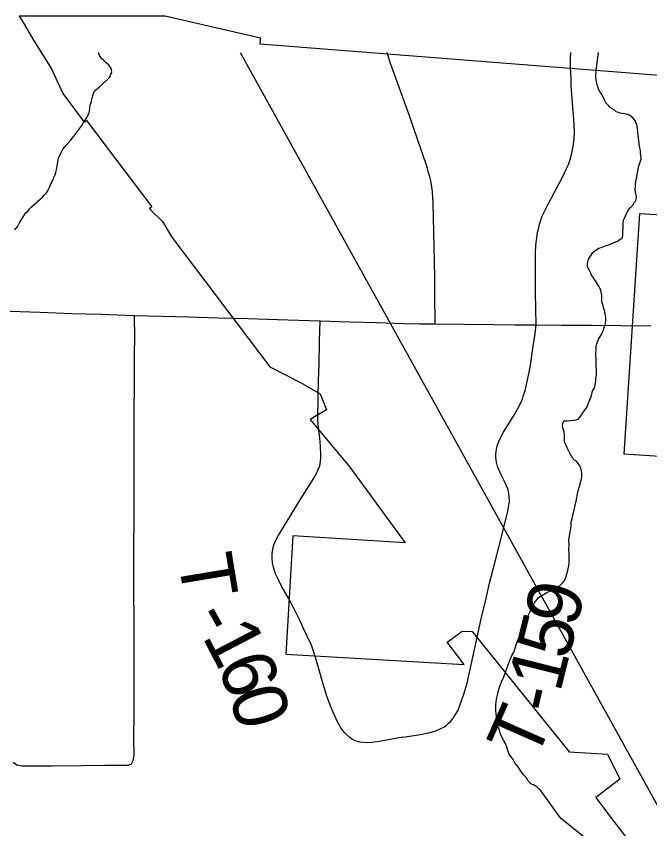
# Model space of a CAD drawing. Extents: x -11.4 to 84.1, y 11.1 to 59.
# Drawn here: x 27.637 to 28.301, y 46.596 to 47.448 of the extents above; entities that cross this region are included whole.
import ezdxf

# ---------------------------------------------------------------- set-up
doc = ezdxf.new("R2010")
doc.units = 0
for name, color, linetype in [('GM_X_Corporation', 7, 'Continuous'), ('GM_X_Minor_River', 7, 'Continuous'), ('GM_X_Rail_Line', 7, 'Continuous'), ('GM_X_Township_Road', 7, 'Continuous'), ('GM_X_Township_Road_Text', 7, 'Continuous')]:
    doc.layers.add(name, color=color, linetype=linetype)

msp = doc.modelspace()

# ---------------------------------------------------------------- linework, layer by layer
at = {"layer": 'GM_X_Corporation'}
msp.add_line((27.79268, 47.44833), (27.63977, 47.44833), dxfattribs=at)
for points in [[(27.63977, 47.44833), (27.64249, 47.4443), (27.6547, 47.42315), (27.67347, 47.39312), (27.68548, 47.36738), (27.70805, 47.33744), (27.71029, 47.33919), (27.77869, 47.24846), (27.77645, 47.24671), (27.77782, 47.2449), (27.78994, 47.23319), (27.79979, 47.2168), (27.90239, 47.08071), (27.93479, 47.06422), (27.95529, 47.05239), (27.96203, 47.03571), (27.95104, 47.02936), (27.94478, 47.02544), (27.98632, 46.97547), (28.04447, 46.89618), (27.92669, 46.90354), (27.91934, 46.77964), (28.1062, 46.76855), (28.08852, 46.79203), (28.1041, 46.80376), (28.11456, 46.8031), (28.21645, 46.67717), (28.25658, 46.67474), (28.26956, 46.64831), (28.24424, 46.62928), (28.25971, 46.6087), (28.38036, 46.45198)], [(28.44546, 47.44833), (28.44455, 47.44112), (28.53898, 47.43662), (28.53548, 47.37236), (28.42679, 47.37725), (27.89224, 47.41905), (27.89257, 47.4253), (27.79268, 47.44833)], [(28.2903, 47.24157), (28.42072, 47.2334), (28.42172, 47.24957), (28.5648, 47.24008), (28.55737, 47.12683), (28.7946, 47.11346), (28.77683, 46.76871), (28.73379, 46.77147), (28.74706, 46.99577), (28.65864, 47.00186), (28.65525, 46.95254), (28.60594, 46.95577), (28.60858, 47.01026), (28.59714, 47.01103), (28.59712, 47.01103), (28.59707, 47.01009), (28.49816, 47.01681), (28.40014, 47.02337), (28.39736, 46.98115), (28.27402, 46.98922), (28.2903, 47.24157)]]:
    msp.add_lwpolyline(points, dxfattribs=at)
at = {"layer": 'GM_X_Minor_River'}
for points in [[(27.63524, 47.22449), (27.63824, 47.22832), (27.6401, 47.23176), (27.64234, 47.2352), (27.64458, 47.23903), (27.64682, 47.24209), (27.6487, 47.24401), (27.6502, 47.24593), (27.65283, 47.24862), (27.66148, 47.25631), (27.66412, 47.25861), (27.66637, 47.26092), (27.66825, 47.26322), (27.67011, 47.2659), (27.67123, 47.26819), (27.67234, 47.27086), (27.67345, 47.27315), (27.67494, 47.27621), (27.67604, 47.27926), (27.67753, 47.28194), (27.67826, 47.28461), (27.67899, 47.28728), (27.6797, 47.29147), (27.68042, 47.29527), (27.68113, 47.29947), (27.68261, 47.30328), (27.68409, 47.30634), (27.68558, 47.30901), (27.68745, 47.31131), (27.68971, 47.314), (27.69308, 47.31783), (27.69571, 47.3209), (27.69833, 47.32435), (27.70095, 47.32742), (27.70319, 47.33086), (27.70544, 47.33392), (27.70768, 47.33775), (27.70954, 47.34043), (27.71066, 47.34234), (27.71178, 47.34425), (27.7129, 47.34617), (27.71363, 47.34883), (27.71397, 47.35188), (27.71431, 47.35531), (27.71541, 47.35912), (27.71613, 47.36293), (27.71723, 47.36636), (27.71834, 47.36903), (27.72021, 47.37133), (27.7236, 47.37403), (27.733, 47.38287), (27.73489, 47.3844), (27.73599, 47.38746), (27.73673, 47.38937), (27.7367, 47.39203), (27.73591, 47.3943), (27.7336, 47.39694), (27.73091, 47.39957), (27.72898, 47.40145), (27.7263, 47.40371), (27.72398, 47.40711), (27.72319, 47.40938), (27.72318, 47.41026)], [(28.28767, 47.28271), (28.28839, 47.28576), (28.2891, 47.29033), (28.29167, 47.29834), (28.29164, 47.30062), (28.29122, 47.30442), (28.29118, 47.30746), (28.29039, 47.31049), (28.28958, 47.31429), (28.28916, 47.31809), (28.28872, 47.32302), (28.28829, 47.3272), (28.28788, 47.33024), (28.28747, 47.3329), (28.28706, 47.33517), (28.28628, 47.33707), (28.28549, 47.33896), (28.28318, 47.34198), (28.27973, 47.34422), (28.27782, 47.34535), (28.27477, 47.34608), (28.27172, 47.34642), (28.26982, 47.34679), (28.26791, 47.34753), (28.26562, 47.34827), (28.2637, 47.34977), (28.2614, 47.35126), (28.2591, 47.35276), (28.25756, 47.35465), (28.25486, 47.35766), (28.2537, 47.35955), (28.25253, 47.3622), (28.25097, 47.36599), (28.24865, 47.36863), (28.24709, 47.37203), (28.24591, 47.37544), (28.24511, 47.37962), (28.24428, 47.38531), (28.24459, 47.3914), (28.24701, 47.41026)], [(28.21265, 46.99909), (28.21148, 47.00213), (28.21145, 47.00441), (28.21143, 47.00631), (28.2114, 47.00859), (28.21138, 47.01049), (28.21058, 47.0139), (28.20978, 47.01694), (28.20937, 47.01959), (28.20973, 47.0215), (28.21084, 47.02417), (28.21388, 47.0242), (28.22375, 47.02506), (28.22565, 47.02584), (28.22828, 47.02853), (28.22976, 47.03158), (28.23238, 47.03503), (28.235, 47.03886), (28.23684, 47.04382), (28.23907, 47.04878), (28.24089, 47.05527), (28.24275, 47.05871), (28.24348, 47.06138), (28.24383, 47.06404), (28.24419, 47.06595), (28.24416, 47.06823), (28.24452, 47.07013), (28.24486, 47.07356), (28.24481, 47.07774), (28.24475, 47.08268), (28.24469, 47.08838), (28.24424, 47.09408), (28.24456, 47.09979), (28.24452, 47.10245), (28.24562, 47.10588), (28.2471, 47.1097), (28.25008, 47.11467), (28.25231, 47.11963), (28.25377, 47.12421), (28.25486, 47.1284), (28.25482, 47.13259), (28.25442, 47.13448), (28.25401, 47.13638), (28.25321, 47.13979), (28.25242, 47.14283), (28.25162, 47.14624), (28.25044, 47.14927), (28.25042, 47.15155), (28.25038, 47.15421), (28.25036, 47.15611), (28.24995, 47.15877), (28.24954, 47.16143), (28.24838, 47.16332), (28.24722, 47.16521), (28.24605, 47.16748), (28.2445, 47.16974), (28.24102, 47.17503), (28.23986, 47.17692), (28.23908, 47.17881), (28.23752, 47.18184), (28.23635, 47.18411), (28.23557, 47.18638), (28.23554, 47.18866), (28.23589, 47.19095), (28.23662, 47.19362), (28.23849, 47.19668), (28.2411, 47.2005), (28.24449, 47.20358), (28.24751, 47.20513), (28.24978, 47.20591), (28.25168, 47.20669), (28.25508, 47.20787), (28.25849, 47.20904), (28.26265, 47.2106), (28.26681, 47.21255), (28.26983, 47.21448), (28.27172, 47.21526), (28.27244, 47.21869), (28.2724, 47.22249), (28.27273, 47.22667), (28.27305, 47.232), (28.2734, 47.23467), (28.27451, 47.23734), (28.27525, 47.23924), (28.27673, 47.2423), (28.2786, 47.24536), (28.28085, 47.24804), (28.2831, 47.25035), (28.28459, 47.25302), (28.28609, 47.25494), (28.28645, 47.25684), (28.2868, 47.25913), (28.2864, 47.26103), (28.28599, 47.26369), (28.28557, 47.26672), (28.28592, 47.26977), (28.28589, 47.27205), (28.28624, 47.27433), (28.28659, 47.277), (28.28732, 47.27967), (28.28767, 47.28271)], [(28.20688, 46.60833), (28.18607, 46.63688), (28.18261, 46.63989), (28.17878, 46.64251), (28.1761, 46.64363), (28.17302, 46.64702), (28.17109, 46.65004), (28.16839, 46.65306), (28.16569, 46.65683), (28.16297, 46.66136), (28.1595, 46.66551), (28.15679, 46.67005), (28.15486, 46.67269), (28.15293, 46.67533), (28.15213, 46.67836), (28.15095, 46.68216), (28.14938, 46.68594), (28.14744, 46.68934), (28.1455, 46.69313), (28.14393, 46.69691), (28.14275, 46.7007), (28.14157, 46.70411), (28.1399, 46.71664), (28.13947, 46.72082), (28.13941, 46.72652), (28.1401, 46.73223), (28.14119, 46.73643), (28.14191, 46.73986), (28.14338, 46.74481), (28.14521, 46.75053), (28.14781, 46.75588), (28.14966, 46.76046), (28.15223, 46.76847), (28.15444, 46.77382), (28.15629, 46.77802), (28.15816, 46.78146), (28.15963, 46.78566), (28.1611, 46.79023), (28.16294, 46.79481), (28.16442, 46.79863), (28.16589, 46.80283), (28.16774, 46.80741), (28.16922, 46.81122), (28.17106, 46.81619), (28.17329, 46.82001), (28.17553, 46.82421), (28.17702, 46.82689), (28.17814, 46.8288), (28.17887, 46.83109), (28.18035, 46.83415), (28.1826, 46.83683), (28.1841, 46.83875), (28.1875, 46.84106), (28.18938, 46.84222), (28.19278, 46.84416), (28.19618, 46.84571), (28.19959, 46.84727), (28.20262, 46.84844), (28.2045, 46.8496), (28.20676, 46.8519), (28.20902, 46.85382), (28.21089, 46.85612), (28.21238, 46.85918), (28.21384, 46.86376), (28.2153, 46.86909), (28.21638, 46.87443), (28.21633, 46.87899), (28.21627, 46.88431), (28.21583, 46.88925), (28.21615, 46.8942), (28.21609, 46.89952), (28.21821, 46.91323), (28.21854, 46.91779), (28.21962, 46.92313), (28.22034, 46.92656), (28.22107, 46.92922), (28.22179, 46.93227), (28.22251, 46.93608), (28.2236, 46.93989), (28.22432, 46.94332), (28.22504, 46.94751), (28.22612, 46.95209), (28.22722, 46.95552), (28.22795, 46.95819), (28.22868, 46.96086), (28.22904, 46.96314), (28.22939, 46.96581), (28.22972, 46.96999), (28.22892, 46.97264), (28.22852, 46.97492), (28.22736, 46.97681), (28.2258, 46.97946), (28.22388, 46.98172), (28.2212, 46.98321), (28.22003, 46.98548), (28.2181, 46.98812), (28.21616, 46.99153), (28.21421, 46.99569), (28.21265, 46.99909)], [(28.20688, 46.60833), (28.23212, 46.58796)]]:
    msp.add_lwpolyline(points, dxfattribs=at)
at = {"layer": 'GM_X_Rail_Line'}
msp.add_lwpolyline([(27.87133, 47.41026), (28.31469, 46.60998), (28.35442, 46.5561), (28.38709, 46.51724), (28.411, 46.50365), (28.46901, 46.49304), (28.59999, 46.44188), (28.7266, 46.38884), (28.90686, 46.29962), (28.96424, 46.27341), (29.02225, 46.26967), (29.04408, 46.28589), (29.07776, 46.34829), (29.09959, 46.38323), (29.13452, 46.40756), (29.16446, 46.41567), (29.23369, 46.40569), (29.32475, 46.39009), (29.40646, 46.38884)], dxfattribs=at)
at = {"layer": 'GM_X_Township_Road'}
for points in [[(28.07597, 47.12574), (28.07554, 47.15681), (28.0753, 47.17394), (28.07506, 47.19107), (28.07436, 47.22185), (28.07366, 47.25264), (28.07347, 47.25773), (28.07286, 47.26451), (28.07229, 47.269), (28.07111, 47.27569), (28.07012, 47.28012), (28.06899, 47.28451), (28.06771, 47.28885), (28.06629, 47.29315), (28.05752, 47.31856), (28.04876, 47.34397), (28.03875, 47.37195), (28.02875, 47.39995), (28.02538, 47.41026)], [(28.18157, 47.12471), (28.18136, 47.14178), (28.18114, 47.15885), (28.18102, 47.17637), (28.1809, 47.1939), (28.18109, 47.20042), (28.18133, 47.20804), (28.18152, 47.2116), (28.18247, 47.2158), (28.1829, 47.21941), (28.18338, 47.22299), (28.18438, 47.2268), (28.18523, 47.23051), (28.18666, 47.23446), (28.18776, 47.23808), (28.18971, 47.24227), (28.19268, 47.24786), (28.19439, 47.25122), (28.19771, 47.25808), (28.20966, 47.28037), (28.21356, 47.28879), (28.21581, 47.29374), (28.21723, 47.29812), (28.21828, 47.30203), (28.21985, 47.30798), (28.22099, 47.31465), (28.22147, 47.31955), (28.22171, 47.32664), (28.22119, 47.34017), (28.22023, 47.35307), (28.21914, 47.36631), (28.21851, 47.37469), (28.21841, 47.37908), (28.21823, 47.38359), (28.21804, 47.3883), (28.21761, 47.39549), (28.21776, 47.4052), (28.21797, 47.41026)], [(27.63039, 47.139), (27.66144, 47.13797), (27.67812, 47.13741), (27.69478, 47.13685), (27.72583, 47.13582), (27.74318, 47.13524), (27.76053, 47.13467), (27.78897, 47.13395), (27.81743, 47.13322), (27.84848, 47.13226), (27.87954, 47.13129), (27.91059, 47.13033), (27.93301, 47.12963), (27.95543, 47.12893), (27.98649, 47.12798), (28.0146, 47.12712), (28.04271, 47.12626), (28.05934, 47.126), (28.07597, 47.12574), (28.10661, 47.12537), (28.13723, 47.125), (28.1594, 47.12485), (28.18157, 47.12471), (28.20859, 47.12461), (28.23966, 47.12433), (28.27073, 47.12406), (28.3018, 47.12379)], [(27.75735, 46.66451), (27.75887, 46.66743), (27.75999, 46.67115), (27.76019, 46.67445), (27.76004, 46.69019), (27.76021, 46.7196), (27.76038, 46.749), (27.76015, 46.82017), (27.76007, 46.83999), (27.75999, 46.8598), (27.76007, 46.89087), (27.76016, 46.92194), (27.76025, 46.95301), (27.76034, 46.98408), (27.76043, 47.01515), (27.76068, 47.07957), (27.76075, 47.09527), (27.76083, 47.11096), (27.76053, 47.13467)], [(28.04191, 46.69236), (28.01712, 46.68809), (28.00931, 46.68691), (28.0048, 46.68663), (28.00051, 46.68682), (27.99672, 46.68727), (27.99183, 46.6886), (27.98928, 46.68997), (27.98622, 46.6922), (27.98316, 46.69476), (27.98115, 46.6969), (27.97878, 46.69992), (27.97632, 46.70352), (27.97335, 46.70854), (27.9681, 46.72023), (27.96536, 46.72722), (27.96276, 46.73447), (27.95833, 46.74803), (27.95377, 46.764), (27.94947, 46.77966), (27.94783, 46.78386), (27.94605, 46.78883), (27.94163, 46.79851), (27.93747, 46.80709), (27.93386, 46.81499), (27.92802, 46.8269), (27.92213, 46.83808), (27.91447, 46.85146), (27.91132, 46.85808), (27.90964, 46.86172), (27.90858, 46.86387), (27.90725, 46.86711), (27.90619, 46.87063), (27.90529, 46.87531), (27.90492, 46.88008), (27.90506, 46.88485), (27.90577, 46.88958), (27.90684, 46.89423), (27.9089, 46.89906), (27.91099, 46.90286), (27.91396, 46.90824), (27.92334, 46.92339), (27.93272, 46.93854), (27.94856, 46.96411), (27.95176, 46.96972), (27.95326, 46.97296), (27.95441, 46.97615), (27.95513, 46.9788), (27.95573, 46.98168), (27.95587, 46.98529), (27.95605, 46.98926), (27.95568, 46.99683), (27.95524, 47.00233), (27.95441, 47.00875), (27.95328, 47.02044), (27.95277, 47.02588), (27.95308, 47.0501), (27.95358, 47.06646), (27.95408, 47.08283), (27.95459, 47.10734), (27.95543, 47.12893)], [(28.04191, 46.69236), (28.05818, 46.69504), (28.07044, 46.69751), (28.07635, 46.69926), (28.08123, 46.70125), (28.0855, 46.70336), (28.08765, 46.70504), (28.08941, 46.70682), (28.09228, 46.70915), (28.09455, 46.71225), (28.09718, 46.7161), (28.09976, 46.72068), (28.10208, 46.72657), (28.10555, 46.73652), (28.1092, 46.74922), (28.11356, 46.76845), (28.11792, 46.78768), (28.12413, 46.81643), (28.12852, 46.83511), (28.13292, 46.85379), (28.13908, 46.87809), (28.14524, 46.90238), (28.15182, 46.92928), (28.15308, 46.9357), (28.15382, 46.93996), (28.15318, 46.94822), (28.15218, 46.95165), (28.14957, 46.95841), (28.14571, 46.96628), (28.14234, 46.97365), (28.14118, 46.97644), (28.14018, 46.98086), (28.13955, 46.98565), (28.13945, 46.98928), (28.13971, 46.99249), (28.14034, 46.99591), (28.14118, 46.99907), (28.1435, 47.00497), (28.14734, 47.01223), (28.15886, 47.03072), (28.16255, 47.03713), (28.16408, 47.04008), (28.16529, 47.04255), (28.16651, 47.04518), (28.16761, 47.04813), (28.1685, 47.05097), (28.1695, 47.05398), (28.1704, 47.05687), (28.17161, 47.06229), (28.17524, 47.08018), (28.17855, 47.10255), (28.18066, 47.11556), (28.18157, 47.12471)], [(27.63337, 46.66622), (27.63746, 46.66352), (27.64311, 46.66237), (27.67418, 46.66258), (27.70524, 46.66279), (27.72956, 46.66295), (27.75388, 46.66312), (27.75735, 46.66451)]]:
    msp.add_lwpolyline(points, dxfattribs=at)

# ---------------------------------------------------------------- texts
at = {"layer": 'GM_X_Township_Road_Text'}
for s, rotation, p in [('T', 279.45387, (27.80596, 46.88009)), ('9', 76.2111, (28.22365, 46.80631)), ('-', 299.19558, (27.81997, 46.81812)), ('5', 76.15269, (28.21526, 46.77227)), ('1', 297.55422, (27.83114, 46.79813)), ('6', 291.55499, (27.84668, 46.76853)), ('1', 75.95996, (28.20672, 46.73811)), ('0', 286.91756, (27.85914, 46.73712)), ('-', 76.67818, (28.20139, 46.71559)), ('T', 66.19025, (28.18062, 46.66597))]:
    msp.add_text(s, height=0.05682, rotation=rotation, dxfattribs=at).set_placement(p)

doc.saveas('drawing.dxf')
